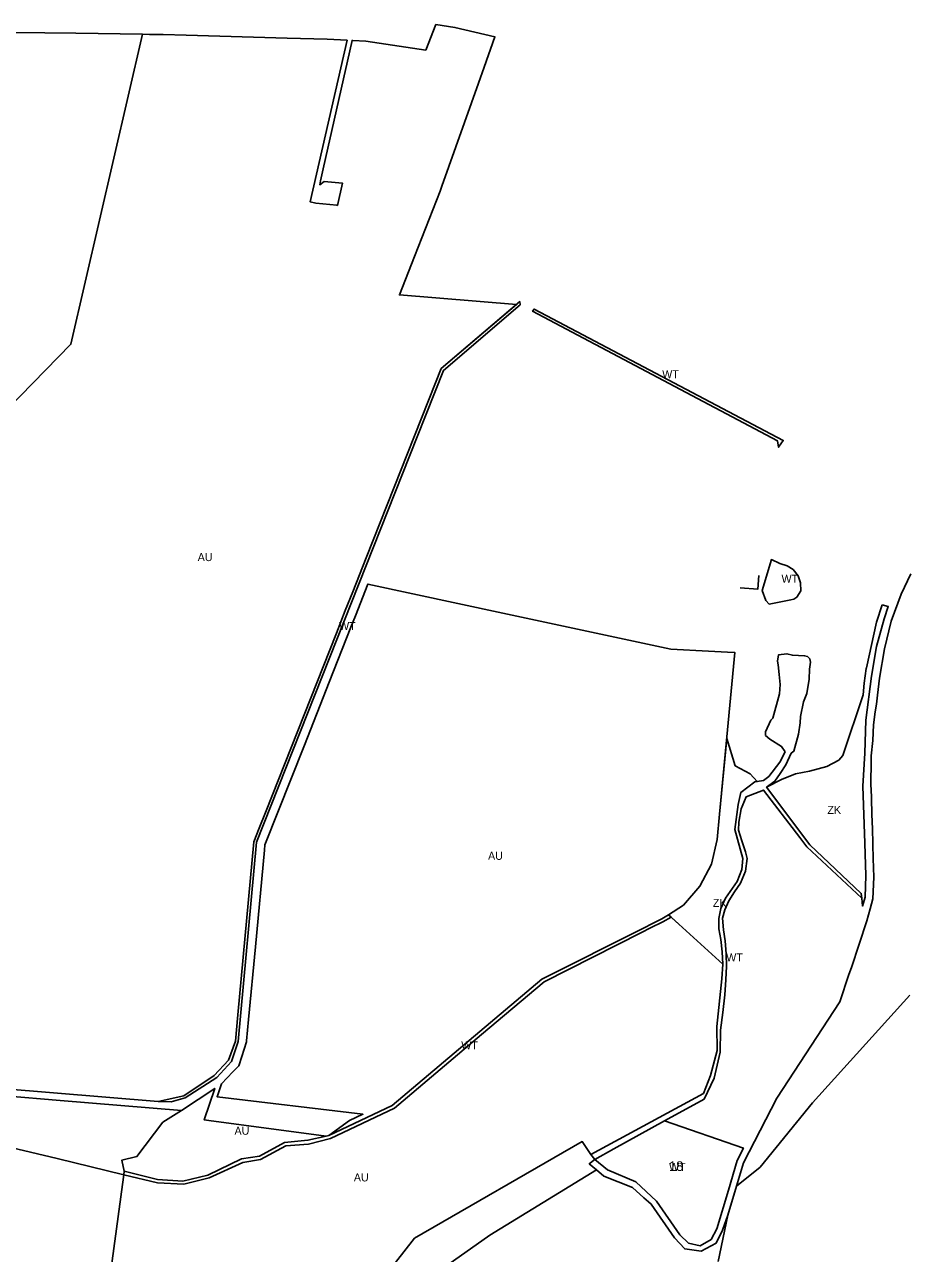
# Model space of a CAD drawing. Extents: x -541351 to -537540, y -1162694 to -1159725.
# Drawn here: x -538734 to -538183, y -1162094 to -1161326 of the extents above; entities that cross this region are included whole.
import ezdxf

# ---------------------------------------------------------------- set-up
doc = ezdxf.new("R2010")
doc.units = 0
for name, color, linetype in [('90640013', 7, 'Continuous'), ('90640023', 7, 'Continuous'), ('90710013', 7, 'Continuous'), ('90730013', 7, 'Continuous'), ('90730023', 7, 'Continuous'), ('90750013', 7, 'Continuous'), ('90770013', 7, 'Continuous'), ('90910012', 7, 'Continuous'), ('ID_navrh', 7, 'Continuous')]:
    doc.layers.add(name, color=color, linetype=linetype)

msp = doc.modelspace()

# ---------------------------------------------------------------- linework, layer by layer
at = {"layer": '90640013'}
for points in [[(-538424.71, -1161499.28), (-538424.71, -1161499.28), (-538424.57, -1161501.23), (-538472.42, -1161542.27), (-538488.863, -1161583.734), (-538488.863, -1161583.734), (-538589.29, -1161836.98), (-538600.78, -1161961.59), (-538605, -1161974.15), (-538614, -1161984.1), (-538633.82, -1161996.81), (-538642.69, -1161999.35), (-538650.79, -1161999.07), (-538634.63, -1161995.5), (-538615.69, -1161982.82), (-538606.71, -1161973.27), (-538602.52, -1161961.34), (-538601, -1161944.96), (-538590.94, -1161836.83), (-538587.57, -1161828.3), (-538583.65, -1161818.41), (-538539.36, -1161706.5), (-538533.77, -1161692.37), (-538529.12, -1161680.62), (-538520.68, -1161659.3), (-538477.43, -1161550.01), (-538473.93, -1161541.16)], [(-538415.779, -1161503.987), (-538415.779, -1161503.987), (-538260.04, -1161586.07), (-538262.93, -1161590.34), (-538263.69, -1161586.22), (-538416.71, -1161505.29), (-538416.71, -1161505.29)], [(-538257.5, -1161664.33), (-538253.79, -1161666.73), (-538250.71, -1161670.68), (-538249.33, -1161674.98), (-538249, -1161679.94), (-538251.52, -1161683.9), (-538253.52, -1161685.22), (-538255.36, -1161685.69), (-538268.88, -1161688.31), (-538270.86, -1161686.12), (-538273.23, -1161679.79), (-538267.41, -1161660.47), (-538262.12, -1161662.84)], [(-538258.79, -1161780.69), (-538261.12, -1161777.24), (-538268.45, -1161772.76), (-538271.09, -1161770.32), (-538271.08, -1161768.03), (-538267.72, -1161760.88), (-538266.54, -1161759.66), (-538262.47, -1161744.28), (-538262, -1161738.48), (-538262.59, -1161732.24), (-538263.18, -1161726.3), (-538263.68, -1161723.89), (-538262.99, -1161719.99), (-538257.76, -1161719.32), (-538254.34, -1161720.22), (-538246.7, -1161720.57), (-538244.86, -1161721.08), (-538243.43, -1161722.42), (-538243, -1161724.65), (-538243.7, -1161728.99), (-538243.88, -1161735.22), (-538245.33, -1161744.12), (-538247.3, -1161749.42), (-538249.25, -1161758.49), (-538249.48, -1161762.51), (-538250.47, -1161769.56), (-538253.43, -1161780.27), (-538255.16, -1161781.52), (-538258.35, -1161788.8), (-538261.97, -1161794.15), (-538265.4, -1161798.93), (-538270.48, -1161802.78), (-538243.44, -1161838.72), (-538211.32, -1161869.1), (-538211, -1161872.06), (-538245.31, -1161839.93), (-538249.75, -1161834.12), (-538272.33, -1161804.55), (-538283.29, -1161808.73), (-538286.3, -1161816.2), (-538287.84, -1161824.45), (-538288.04, -1161829.55), (-538285.85, -1161836.25), (-538283.57, -1161843.03), (-538282.58, -1161847.31), (-538283.72, -1161855.08), (-538286.78, -1161862.58), (-538290.52, -1161868.06), (-538294.04, -1161873.72), (-538296.64, -1161879.41), (-538297.95, -1161884.55), (-538297.4, -1161891.73), (-538296.38, -1161898.65), (-538295.66, -1161906.72), (-538295.58, -1161914.62), (-538296.02, -1161923.01), (-538296.59, -1161932.38), (-538297.86, -1161943.46), (-538299.26, -1161954.57), (-538299.41, -1161968.27), (-538303.15, -1161984.49), (-538309.41, -1161997.57), (-538334.17, -1162011.19), (-538365.98, -1162028.7), (-538377.86, -1162035.24), (-538380.39, -1162032.29), (-538309.83, -1161994.08), (-538305.44, -1161982.77), (-538301.41, -1161967.16), (-538301.47, -1161952.23), (-538298.36, -1161922.4), (-538297.88, -1161913.34), (-538298.12, -1161905.57), (-538298.96, -1161897.77), (-538300.34, -1161891.15), (-538300.4, -1161884.83), (-538298.96, -1161878.49), (-538296.07, -1161871.99), (-538288.92, -1161861.58), (-538285.91, -1161854.09), (-538285.31, -1161847.35), (-538290.36, -1161829.15), (-538288.32, -1161813.47), (-538286.52, -1161805.95), (-538277.8, -1161799.39), (-538276.25, -1161799.16), (-538272.29, -1161798.57), (-538269.1, -1161796.05), (-538262.18, -1161787.08)], [(-538335.271, -1161886.901), (-538342.98, -1161890.59), (-538342.98, -1161890.59), (-538348.56, -1161893.55), (-538409.5, -1161924.28), (-538448.62, -1161957.3), (-538503.11, -1162003.3), (-538543.06, -1162022.21), (-538556.83, -1162025.7), (-538570.89, -1162026.74), (-538586.69, -1162035.26), (-538597.81, -1162037.26), (-538618.79, -1162046.68), (-538634.78, -1162050.76), (-538651.26, -1162049.9), (-538672.267, -1162044.823), (-538672.267, -1162044.823), (-538671.98, -1162042.69), (-538651.07, -1162047.91), (-538635.3, -1162048.81), (-538619.76, -1162045.01), (-538598.67, -1162034.88), (-538587.5, -1162033.14), (-538571.7, -1162024.63), (-538557.2, -1162023.33), (-538545.8, -1162020.73), (-538544.04, -1162020.34), (-538504.49, -1162001.62), (-538410.88, -1161922.6), (-538347.4, -1161890.75), (-538341.68, -1161887.88), (-538335.88, -1161884.94), (-538331.82, -1161882.37), (-538330.078, -1161883.957)]]:
    msp.add_lwpolyline(points, close=True, dxfattribs=at)
at = {"layer": '90640023'}
msp.add_lwpolyline([(-538334.17, -1162011.19), (-538284.97, -1162028.18), (-538288.78, -1162035.88), (-538294.3, -1162054.42), (-538301.51, -1162078.63), (-538305.14, -1162085.3), (-538312.04, -1162089.17), (-538319.3, -1162087.53), (-538324.69, -1162082.49), (-538339.31, -1162061.37), (-538352.19, -1162049.19), (-538369.87, -1162041.81), (-538377.86, -1162035.24), (-538365.98, -1162028.7)], close=True, dxfattribs=at)
at = {"layer": '90710013'}
for points in [[(-538198.16, -1161688.686), (-538194.387, -1161689.903), (-538194.387, -1161689.903), (-538197.05, -1161697.53), (-538201.67, -1161714.79), (-538204.78, -1161733.41), (-538208.38, -1161760.87), (-538209.13, -1161781.4), (-538210.23, -1161802.12), (-538209, -1161837.65), (-538208.38, -1161857.93), (-538208.88, -1161871.32), (-538210.46, -1161876.94), (-538211, -1161872.06), (-538211.32, -1161869.1), (-538243.44, -1161838.72), (-538270.48, -1161802.78), (-538261.12, -1161797.97), (-538252.45, -1161794.29), (-538243.63, -1161792.64), (-538232.71, -1161789.76), (-538225.4, -1161785.83), (-538222.78, -1161782.94), (-538210.16, -1161744.89), (-538209.4, -1161737.76), (-538208.14, -1161728.64), (-538208.02, -1161728.1), (-538201.83, -1161699.49)], [(-538290.07, -1161789.43), (-538283.81, -1161792.69), (-538280.77, -1161794.28), (-538276.25, -1161799.16), (-538277.8, -1161799.39), (-538286.52, -1161805.95), (-538288.32, -1161813.47), (-538290.36, -1161829.15), (-538285.31, -1161847.35), (-538285.91, -1161854.09), (-538288.92, -1161861.58), (-538296.07, -1161871.99), (-538298.96, -1161878.49), (-538300.4, -1161884.83), (-538300.34, -1161891.15), (-538298.96, -1161897.77), (-538298.12, -1161905.57), (-538297.88, -1161913.34), (-538325.41, -1161888.21), (-538331.82, -1161882.37), (-538322.45, -1161876.44), (-538312.18, -1161864.56), (-538304.81, -1161850.7), (-538301.4, -1161835.38), (-538299.79, -1161819.56), (-538295.34, -1161772.3)]]:
    msp.add_lwpolyline(points, close=True, dxfattribs=at)
msp.add_lwpolyline([(-538502.37, -1162099.588), (-538490.468, -1162084.494), (-538385.682, -1162024.103), (-538380.39, -1162032.29), (-538377.86, -1162035.24), (-538381.26, -1162037.97), (-538376.785, -1162041.759), (-538443.532, -1162082.673), (-538480.243, -1162108.669)], dxfattribs=at)
at = {"layer": '90730013'}
msp.add_lwpolyline([(-538636.08, -1162004.76), (-538644.52, -1162009.98), (-538647.92, -1162012.08), (-538664.06, -1162033.48), (-538673.38, -1162035.73), (-538671.98, -1162042.69), (-538672.267, -1162044.823), (-538672.267, -1162044.823), (-538713.86, -1162034.77), (-538772.02, -1162020.88), (-538796.41, -1162018.51), (-538803.58, -1162020.1), (-538804.26, -1162018.41), (-538816.04, -1162027.52), (-538822.45, -1162030.47), (-538826.9, -1162032.51), (-538863.08, -1162039.76), (-538815.36, -1161989.8), (-538711.96, -1161998.43)], close=True, dxfattribs=at)
at = {"layer": '90730023'}
for points in [[(-538838.005, -1161625.799), (-538827.847, -1161576.385), (-538798.665, -1161434.423), (-538795.685, -1161419.928), (-538790.55, -1161394.945), (-538777.276, -1161330.371), (-538764.566, -1161330.69), (-538760.434, -1161330.846), (-538702.278, -1161331.538), (-538660.482, -1161332.245), (-538705.32, -1161525.94), (-538744.9, -1161566.45), (-538797.48, -1161620.29)], [(-538713.86, -1162034.77), (-538672.267, -1162044.823), (-538673.105, -1162051.048), (-538695.05, -1162214.09), (-538712.27, -1162226.46), (-538729.02, -1162231.4), (-538730.919, -1162231.96), (-538766.94, -1162179.94), (-538768.78, -1162182.83), (-538771.26, -1162186.72), (-538773.11, -1162183.87), (-538866.22, -1162040.39), (-538863.08, -1162039.76), (-538826.9, -1162032.51), (-538822.45, -1162030.47), (-538816.04, -1162027.52), (-538804.26, -1162018.41), (-538803.58, -1162020.1), (-538796.41, -1162018.51), (-538772.02, -1162020.88)]]:
    msp.add_lwpolyline(points, close=True, dxfattribs=at)
at = {"layer": '90750013'}
for points in [[(-538744.9, -1161566.45), (-538705.32, -1161525.94), (-538660.482, -1161332.245), (-538656.191, -1161332.317), (-538647.722, -1161332.492), (-538633.182, -1161332.902), (-538570.081, -1161334.672), (-538545.041, -1161335.37), (-538532.64, -1161335.957), (-538555.781, -1161436.91), (-538552.25, -1161437.72), (-538539.06, -1161439.12), (-538538.69, -1161439.16), (-538535.47, -1161425.3), (-538547.06, -1161424.15), (-538549.79, -1161426.28), (-538549.28, -1161423.93), (-538547.55, -1161416.25), (-538529.51, -1161336.106), (-538529.042, -1161336.128), (-538520.963, -1161336.51), (-538520.963, -1161336.51), (-538483.483, -1161342.179), (-538477.098, -1161326.205), (-538465.32, -1161327.97), (-538440.24, -1161333.79), (-538446.975, -1161352.758), (-538446.975, -1161352.758), (-538450.58, -1161362.91), (-538473.42, -1161427.27), (-538474.592, -1161430.269), (-538490.548, -1161471.103), (-538490.548, -1161471.103), (-538499.94, -1161495.139), (-538426.861, -1161501.11), (-538473.93, -1161541.16), (-538477.43, -1161550.01), (-538520.68, -1161659.3), (-538529.12, -1161680.62), (-538533.77, -1161692.37), (-538539.36, -1161706.5), (-538583.65, -1161818.41), (-538587.57, -1161828.3), (-538590.94, -1161836.83), (-538601, -1161944.96), (-538602.52, -1161961.34), (-538606.71, -1161973.27), (-538615.69, -1161982.82), (-538634.63, -1161995.5), (-538650.79, -1161999.07), (-538814.6, -1161985.57)], [(-538181.01, -1161932.67), (-538241.75, -1162000), (-538274.52, -1162040.2), (-538289.23, -1162051.98), (-538284.85, -1162037.35), (-538264.1, -1161997.03), (-538224.69, -1161936.84), (-538219.04, -1161919.65), (-538217.39, -1161915.26), (-538207.73, -1161886.21), (-538205.8, -1161878.72), (-538204.12, -1161872.38), (-538203.5, -1161858.98), (-538203.86, -1161847.18), (-538203.96, -1161838.54), (-538203.97, -1161837.63), (-538204.21, -1161829.02), (-538204.57, -1161819.51), (-538204.93, -1161809.73), (-538205.18, -1161803.76), (-538205.3, -1161801.86), (-538205.3, -1161798.05), (-538205.04, -1161789.17), (-538205.03, -1161783.21), (-538204.12, -1161773.43), (-538203.6, -1161763.66), (-538202.56, -1161755.54), (-538201.84, -1161750.78), (-538201.11, -1161745.28), (-538199.78, -1161734.53), (-538196.85, -1161716.26), (-538192.49, -1161698.9), (-538186.37, -1161682.08), (-538180.3, -1161669.35)], [(-538695.05, -1162214.09), (-538673.105, -1162051.048), (-538672.267, -1162044.823), (-538651.26, -1162049.9), (-538634.78, -1162050.76), (-538618.79, -1162046.68), (-538597.81, -1162037.26), (-538586.69, -1162035.26), (-538570.89, -1162026.74), (-538556.83, -1162025.7), (-538543.06, -1162022.21), (-538503.11, -1162003.3), (-538448.62, -1161957.3), (-538409.5, -1161924.28), (-538348.56, -1161893.55), (-538342.98, -1161890.59), (-538342.98, -1161890.59), (-538335.271, -1161886.901), (-538330.078, -1161883.957), (-538325.41, -1161888.21), (-538297.88, -1161913.34), (-538298.36, -1161922.4), (-538301.47, -1161952.23), (-538301.41, -1161967.16), (-538305.44, -1161982.77), (-538309.83, -1161994.08), (-538380.39, -1162032.29), (-538380.39, -1162032.29), (-538385.682, -1162024.103), (-538490.468, -1162084.494), (-538502.37, -1162099.588)], [(-538480.243, -1162108.669), (-538443.532, -1162082.673), (-538376.785, -1162041.759), (-538372.13, -1162045.7), (-538354.33, -1162052.73), (-538347.08, -1162059.2), (-538344.21, -1162061.76), (-538342.6, -1162063.19), (-538327.97, -1162084.29), (-538321.64, -1162091.16), (-538311.25, -1162092.59), (-538302.01, -1162087.53), (-538297.94, -1162079.53), (-538294.68, -1162070.18), (-538300.82, -1162098.99)]]:
    msp.add_lwpolyline(points, dxfattribs=at)
for points in [[(-538331.82, -1161882.37), (-538335.88, -1161884.94), (-538341.68, -1161887.88), (-538347.4, -1161890.75), (-538410.88, -1161922.6), (-538504.49, -1162001.62), (-538544.04, -1162020.34), (-538531.22, -1162010.94), (-538522.78, -1162007.03), (-538613.96, -1161996.08), (-538611.26, -1161988.13), (-538604.09, -1161980.62), (-538600.35, -1161976.7), (-538598.51, -1161970.95), (-538595.61, -1161961.84), (-538595.55, -1161961.24), (-538594.3, -1161947.9), (-538590.02, -1161902.5), (-538584.32, -1161841.97), (-538584.01, -1161838.63), (-538559.39, -1161776.37), (-538543.83, -1161737.06), (-538530.23, -1161702.68), (-538527.46, -1161695.68), (-538519.6, -1161675.81), (-538435.33, -1161693.92), (-538330.29, -1161716.49), (-538306.82, -1161717.74), (-538294.95, -1161718.38), (-538290.276, -1161718.619), (-538290.276, -1161718.619), (-538299.79, -1161819.56), (-538301.4, -1161835.38), (-538304.81, -1161850.7), (-538312.18, -1161864.56), (-538322.45, -1161876.44)], [(-538647.92, -1162012.08), (-538644.52, -1162009.98), (-538636.08, -1162004.76), (-538615.41, -1161990.91), (-538621.98, -1162010.55), (-538619, -1162010.95), (-538545.8, -1162020.73), (-538557.2, -1162023.33), (-538571.7, -1162024.63), (-538587.5, -1162033.14), (-538598.67, -1162034.88), (-538619.76, -1162045.01), (-538635.3, -1162048.81), (-538651.07, -1162047.91), (-538671.98, -1162042.69), (-538673.38, -1162035.73), (-538664.06, -1162033.48)]]:
    msp.add_lwpolyline(points, close=True, dxfattribs=at)
at = {"layer": '90770013'}
msp.add_lwpolyline([(-538300.82, -1162098.99), (-538294.68, -1162070.18), (-538289.23, -1162051.98), (-538274.52, -1162040.2), (-538241.75, -1162000), (-538181.01, -1161932.67)], dxfattribs=at)
at = {"layer": '90910012'}
msp.add_lwpolyline([(-538287.06, -1161678.11), (-538275.87, -1161678.87), (-538275.39, -1161670.47)], dxfattribs=at)

# ---------------------------------------------------------------- texts
at = {"layer": '90640013'}
for rotation, p in [(0, (-538335.698, -1161547.163)), (360, (-538261.115, -1161674.985)), (360, (-538537.68, -1161704.544)), (0, (-538295.695, -1161911.57)), (360, (-538461.279, -1161966.565))]:
    msp.add_text('WT', height=5, rotation=rotation, dxfattribs=at).set_placement(p)
at = {"layer": '90640023'}
msp.add_text('WT', height=5, rotation=0, dxfattribs=at).set_placement((-538331.415, -1162042.458))
at = {"layer": '90710013'}
for rotation, p in [(360, (-538232.433, -1161819.371)), (0, (-538304.035, -1161877.47))]:
    msp.add_text('ZK', height=5, rotation=rotation, dxfattribs=at).set_placement(p)
at = {"layer": '90750013'}
for rotation, p in [(360, (-538626.055, -1161661.431)), (360, (-538603.05, -1162019.86)), (0, (-538528.448, -1162049.023))]:
    msp.add_text('AU', height=5, rotation=rotation, dxfattribs=at).set_placement(p)
msp.add_text('AU', height=5, dxfattribs=at).set_placement((-538444.56, -1161848.075))
at = {"layer": 'ID_navrh'}
msp.add_text('18', height=6, rotation=360, dxfattribs=at).set_placement((-538331.415, -1162042.458))

doc.saveas('drawing.dxf')
